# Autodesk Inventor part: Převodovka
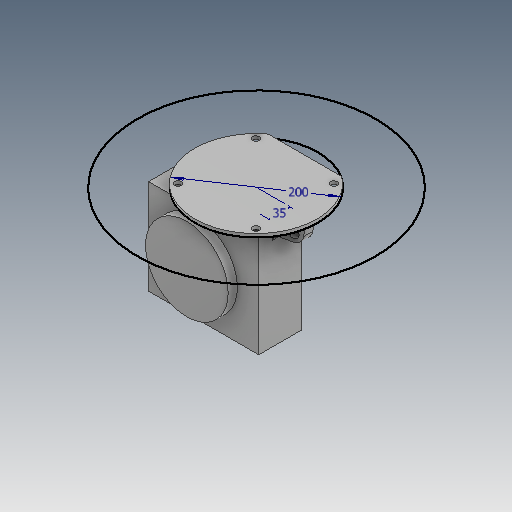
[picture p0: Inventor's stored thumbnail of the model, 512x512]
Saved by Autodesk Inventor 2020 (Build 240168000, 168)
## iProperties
Created: 2025-03
Part Number: Převodovka
Material: Ocel
Document SubType Name: Modeling
Designer: doma
Mass: 16367.5 g
Surface Area: 2511.81 cm^2
Volume: 2085.03 cm^3
Density: 7.85 g/cm^3
Appearance: Hladká – středně šedá
Author: doma
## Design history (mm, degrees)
sketch "Náčrt1"
  geometry: L1 (-77.5, -77.5)-(102.5, -77.5); L2 (102.5, -77.5)-(102.5, 77.5); L3 (102.5, 77.5)-(-77.5, 77.5); L4 (-77.5, 77.5)-(-77.5, -77.5); L5 (-77.5, -77.5)-(102.5, 77.5); L6 (102.5, -77.5)-(-77.5, 77.5); L7 (0, 0)-(12.5, 0); L8 (102.5, 77.5)-(102.5, 122.5); L9 (102.5, 122.5)-(23.5, 122.5); L10 (23.5, 122.5)-(23.5, 77.5); 1 further point
  constraints: 20 end point, 3 perpendicular, 2 horizontal, 2 midpoint, 2 parallel, 1 coincident, 1 point on line, 1 vertical
  dimensions: "d0" = 180 distance of L3.end L2.end; "d1" = 155 distance of L2.end L1.end; "d5" = 12.5 distance of L7.end point (0, 0); "d6" = 79 distance of L8.end L9.end; "d7" = 45 distance between parallel lines of L3 L9
extrude "Vysunutí1" new body sketch "Náčrt1" distance "d8" = 70; taper "d9" = 0 deg
sketch "Náčrt2"
  geometry: C1 r 67.5 at (0, 0); 1 further point
  constraints: 1 centre point, 1 coincident
  dimensions: "d10" = 135 diameter of C1
extrude "Vysunutí2" join sketch "Náčrt2" distance "d11" = 15; taper "d12" = 0 deg
fillet "Zaoblení1" dims "d13" = 10
sketch "Náčrt3"
  geometry: L1 (0, -70)-(0, 0) reference; L2 (79, 0)-(79, -70) reference; L3 (79, -70)-(0, -70) reference; L4 (0, -35)-(79, -35); L5 (79, 0)-(79, -70) reference; L6 (39.5, -70)-(39.5, 0); C1 r 100 at (39.5, -35); C2 r 194.442 at (39.5, -35); 1 further point
  constraints: 4 end point, 4 midpoint, 2 centre point, 1 coincident, 1 vertical
  dimensions: "d14" = 200 diameter of C1; "d16" = 35 distance from line of L3 C1.centre
extrude "Vysunutí3" join sketch "Náčrt3" distance "d17" = 5; taper "d18" = 0 deg
sketch "Náčrt4"
  geometry: C1 r 67.5 at (0, 0); 1 further point
  constraints: 1 centre point, 1 coincident
  dimensions: "d20" = 135 diameter of C1
extrude "Vysunutí4" join sketch "Náčrt4" distance "d21" = 15; taper "d22" = 0 deg
feature "Skořepina1" dims "d23" = 20
sketch "Náčrt6" dims "d43" = 180
  geometry: L1 (0, 0)-(63.64, 63.64); L2 (0, 0)-(90, 0); C1 r 100 at (0, 0) reference; 5 further points
  constraints: 4 end point, 1 coincident, 1 equal length, 1 horizontal, 8 other
  dimensions: "d44" = 45 deg angle of L2 L1; "d47" = 360 deg dimension on point (0, 0) L1.end (derived)
hole "Díra1" sketch "Náčrt6" at (-63.64, -63.64), (-63.64, 63.64), (63.64, 63.64), (63.64, -63.64) diameter "d24" = 11; stored, may be unused: countersink angle "d28" = 90 deg, drill point angle "d30" = 118 deg; dims "d25" = 6, "d26" = 11, "d27" = 6, "d29" = 8
node "Pracovní rovina1"
sketch "Náčrt8"
  geometry: L1 (13.5, 77.5)-(-77.5, 77.5) reference; L2 (13.5, 77.5)-(102.5, 77.5); L3 (102.5, -77.5)-(102.5, 122.5) reference; L4 (102.5, 77.5)-(145.904, 85.153); L5 (102.5, 77.5)-(180.544, 77.5); L6 (152.49, 122.5)-(216.891, 122.5); L7 (152.49, 122.5)-(145.904, 85.153); L8 (102.5, 122.5)-(145.904, 85.153); L9 (163, 122.5)-(-37, 122.5) reference; C1 r 10 at (131.022, 97.959); 1 further point
  constraints: 12 end point, 3 horizontal, 2 point on line, 1 centre point
  dimensions: "d31" = 10 deg angle of L5 L4; "d33" = 20 diameter of C1; "d34" = 80 deg angle of L9 L7; "d35" = 43.4044 horizontal distance of L2.end L4.end
extrude "Vysunutí5" join sketch "Náčrt8" stored distance "d36" = 15; taper "d37" = 0 deg
fillet "Zaoblení3" dims "d38" = 10
fillet "Zaoblení4" dims "d39" = 20
fillet "Zaoblení5" dims "d40" = 5
sketch "Náčrt9"
  geometry: L1 (-82.375, 171.893)-(85.826, 171.893); L2 (85.826, 171.893)-(85.826, 80); L3 (85.826, 80)-(-82.375, 80); L4 (-82.375, 80)-(-82.375, 171.893); C1 r 100 at (0, 0) reference; 1 further point
  constraints: 8 end point, 2 parallel, 1 horizontal, 1 perpendicular
  dimensions: "d49" = 80 distance from line of C1.centre L3
extrude "Vysunutí7" cut sketch "Náčrt9" extent not by distance; stored distance "d50" = 0; taper "d51" = 0 deg
sketch "Náčrt10"
  geometry: C1 r 17.5 at (0, 0); 1 further point
  constraints: 1 centre point, 1 coincident
  dimensions: "d52" = 35 diameter of C1
extrude "Vysunutí8" join sketch "Náčrt10" distance "d53" = 10; taper "d54" = 0 deg
sketch "Náčrt11"
  geometry: C1 r 14 at (0, 0); 1 further point
  constraints: 1 centre point, 1 coincident
  dimensions: "d55" = 28 diameter of C1
extrude "Vysunutí9" join sketch "Náčrt11" distance "d56" = 42; taper "d57" = 0 deg
sketch "Náčrt12"
  geometry: 2 further points
hole "Díra2" sketch "Náčrt12" at (0, 0) diameter "d58" = 6.647; stored, may be unused: countersink angle "d62" = 90 deg, drill point angle "d64" = 118 deg; dims "d59" = 30, "d60" = 4, "d61" = 2, "d63" = 35
node "Těleso1"
other parameters: "d32" = 100 deg
